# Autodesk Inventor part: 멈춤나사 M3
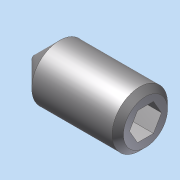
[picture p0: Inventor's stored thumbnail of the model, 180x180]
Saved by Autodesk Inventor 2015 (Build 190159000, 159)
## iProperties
Created: 2026-09
Part Number: 멈춤나사 M3
Material: 일반
Document SubType Name: Modeling
Designer: SCD-A06
Density: 1 g/cm^3
Appearance: 기본값
Author: SCD-A06
Author: jhkim
Description: 6각 소켓 머리 없는 멈춤 나사
Creation Date: 2026-08-27
Sending System: Autodesk Inventor 2027
Preprocessor: ST-DEVELOPER v20.1
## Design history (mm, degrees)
node "멈춤나사 M31"
body "Solid1"
node "기준1"
